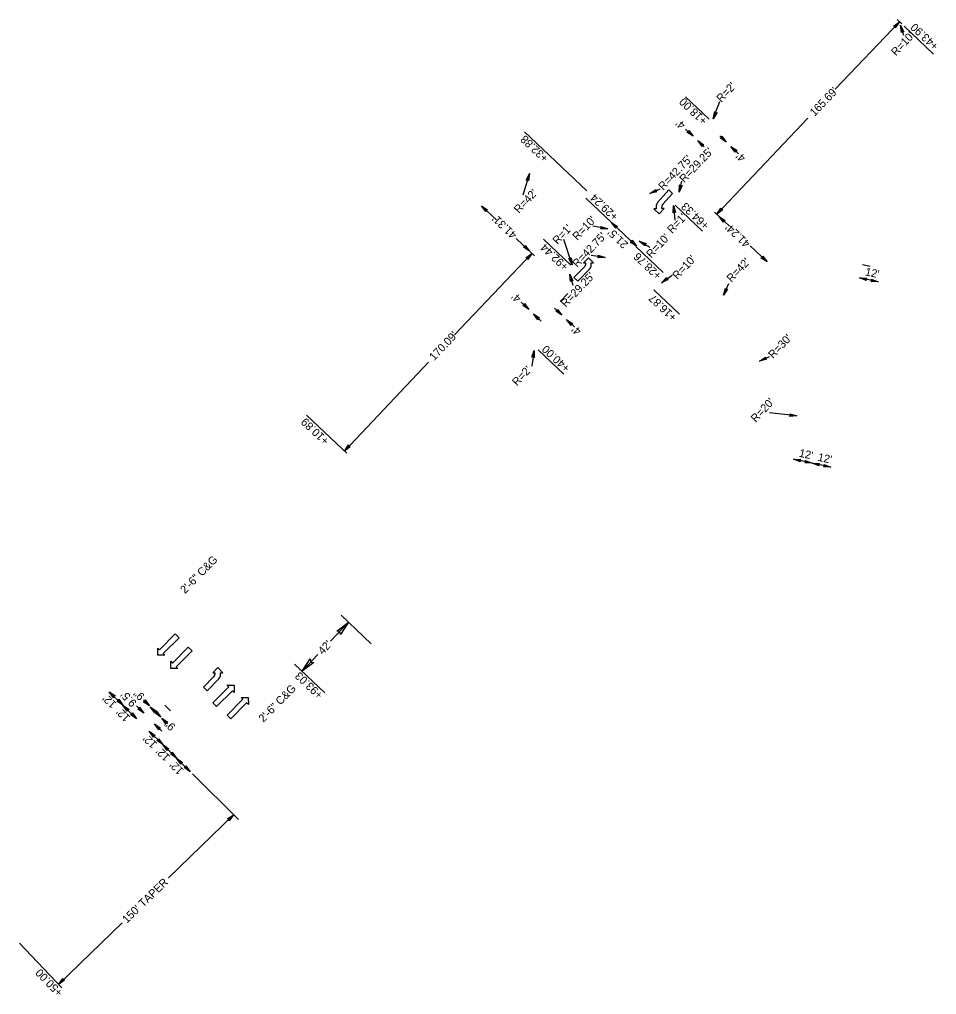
# Model space of a CAD drawing. Extents: x 2320991 to 2332664, y 598057 to 612602.
# Drawn here: x 2327151 to 2327723, y 602418 to 603027 of the extents above; entities that cross this region are included whole.
import ezdxf

# ---------------------------------------------------------------- set-up
doc = ezdxf.new("R2010")
doc.units = 0
for name, color, linetype in [('Prop Dimension', 7, 'Continuous'), ('Prop Dimension Text', 7, 'Continuous'), ('Prop Horizontal Alignment Tick Small', 7, 'Continuous'), ('Prop Lane Arrow CELL', 7, 'Continuous'), ('Prop Terminator CELL', 7, 'Continuous')]:
    doc.layers.add(name, color=color, linetype=linetype)

msp = doc.modelspace()

# ---------------------------------------------------------------- linework, layer by layer
at = {"layer": 'Prop Dimension'}
for p, q in [((2327700.07, 603025.5), (2327660.07, 602983.31)), ((2327701.52, 603024.12), (2327698.62, 603026.87)), ((2327700.84, 603023.33), (2327702.66, 603017)), ((2327702.97, 603022.75), (2327721.44, 603005.24)), ((2327581.34, 602964.58), (2327566.55, 602978.6)), ((2327583.88, 602964.88), (2327587.91, 602975.56)), ((2327642.9, 602965.2), (2327586.07, 602905.26)), ((2327566.56, 602958.44), (2327571.27, 602953.97)), ((2327504.81, 602919.84), (2327465.89, 602956.74)), ((2327587.97, 602954.15), (2327591.96, 602950.35)), ((2327574.17, 602951.21), (2327578.19, 602947.39)), ((2327594.86, 602947.59), (2327599.67, 602943.02)), ((2327469.09, 602930.65), (2327464.93, 602917.11)), ((2327562.55, 602919.06), (2327564.17, 602925.94)), ((2327544.24, 602918.18), (2327550.59, 602921.06)), ((2327439.12, 602910.59), (2327448.5, 602901.69)), ((2327520.27, 602900.17), (2327504.3, 602915.31)), ((2327559.09, 602910.7), (2327559.91, 602901.64)), ((2327560.01, 602910.84), (2327577.1, 602894.64)), ((2327587.52, 602903.88), (2327584.62, 602906.64)), ((2327594, 602897.75), (2327587.52, 602903.88)), ((2327517.95, 602896.18), (2327508.59, 602897.72)), ((2327520.27, 602900.17), (2327535.87, 602885.38)), ((2327460.81, 602890.02), (2327469.1, 602882.17)), ((2327494.95, 602873.46), (2327477.76, 602889.76)), ((2327495.76, 602873.6), (2327490.47, 602889.4)), ((2327537.68, 602888.49), (2327544.31, 602884.76)), ((2327617.45, 602875.51), (2327606.93, 602885.49)), ((2327422.29, 602829.89), (2327470.55, 602880.79)), ((2327469.31, 602881.96), (2327472.22, 602879.21)), ((2327516.32, 602878.3), (2327507.55, 602879.44)), ((2327535.54, 602885.02), (2327552.62, 602868.82)), ((2327494.23, 602867.81), (2327496.16, 602861)), ((2327551.49, 602862.43), (2327558.2, 602867.24)), ((2327590.29, 602854.7), (2327593.54, 602862.02)), ((2327686.9, 602863.02), (2327675.17, 602865.59)), ((2327488.14, 602850.66), (2327492.94, 602855.72)), ((2327546.77, 602857.99), (2327562.81, 602842.79)), ((2327463.98, 602850.24), (2327468.69, 602845.77)), ((2327471.6, 602843.02), (2327476.41, 602838.45)), ((2327484.67, 602846.65), (2327489.38, 602842.18)), ((2327492.29, 602839.43), (2327497.1, 602834.86)), ((2327472.03, 602820.25), (2327470.47, 602810.42)), ((2327474.47, 602820.61), (2327490.44, 602805.47)), ((2327353.53, 602757.36), (2327406.1, 602812.81)), ((2327612.64, 602813.49), (2327618.99, 602816.37)), ((2327352.07, 602758.74), (2327329.88, 602779.77)), ((2327636.13, 602779.33), (2327619.05, 602781.24)), ((2327352.07, 602758.74), (2327354.98, 602755.98)), ((2327645.61, 602749.78), (2327633.88, 602752.35)), ((2327657.33, 602747.22), (2327645.61, 602749.78)), ((2327351.41, 602654.84), (2327370.23, 602636.99)), ((2327344.92, 602638.68), (2327356.06, 602650.43)), ((2327327.09, 602619.88), (2327336.88, 602630.2)), ((2327322.44, 602624.31), (2327341.22, 602606.4)), ((2327206.68, 602607.05), (2327215.21, 602598.61)), ((2327227.97, 602601.9), (2327231.7, 602598.23)), ((2327215.21, 602598.61), (2327223.73, 602590.17)), ((2327223.58, 602598.19), (2327228.21, 602593.62)), ((2327232.23, 602597.7), (2327235.96, 602594.02)), ((2327235.12, 602594.85), (2327238.85, 602591.17)), ((2327234.97, 602586.95), (2327239.59, 602582.38)), ((2327239.39, 602590.64), (2327243.12, 602586.97)), ((2327231.55, 602582.43), (2327240.08, 602573.99)), ((2327240.08, 602573.99), (2327248.61, 602565.54)), ((2327248.61, 602565.54), (2327257.13, 602557.1)), ((2327258.56, 602555.69), (2327287.38, 602527.16)), ((2327243.72, 602490.87), (2327284.31, 602530.19)), ((2327174.97, 602424.29), (2327214.63, 602462.7)), ((2327150.6, 602449.92), (2327176.95, 602422.2))]:
    msp.add_line(p, q, dxfattribs=at)
at = {"layer": 'Prop Horizontal Alignment Tick Small'}
for p, q in [((2327677.02, 602873.85), (2327681.9, 602872.75)), ((2327244.86, 602595.2), (2327241.3, 602598.71))]:
    msp.add_line(p, q, dxfattribs=at)
at = {"layer": 'Prop Lane Arrow CELL'}
for p, q in [((2327556.02, 602920.49), (2327549.02, 602912.6)), ((2327552.41, 602911.46), (2327558.49, 602918.3)), ((2327558.49, 602918.3), (2327556.02, 602920.49)), ((2327548.3, 602908.63), (2327546.81, 602908.54)), ((2327546.81, 602908.54), (2327550.07, 602905.58)), ((2327550.07, 602905.58), (2327553.1, 602908.91)), ((2327553.1, 602908.91), (2327551.61, 602908.83)), ((2327505.97, 602878), (2327502.77, 602874.84)), ((2327502.77, 602874.84), (2327504.25, 602874.84)), ((2327509.06, 602874.87), (2327505.97, 602878)), ((2327507.58, 602874.86), (2327509.06, 602874.87)), ((2327503.31, 602872.26), (2327496.88, 602865.76)), ((2327499.22, 602863.43), (2327506.64, 602870.93)), ((2327496.88, 602865.76), (2327499.22, 602863.43)), ((2327238.01, 602633.22), (2327247.89, 602643.14)), ((2327247.89, 602643.14), (2327250.23, 602640.81)), ((2327250.23, 602640.81), (2327240.35, 602630.89)), ((2327236.99, 602629.79), (2327236.95, 602634.28)), ((2327236.95, 602634.28), (2327238.01, 602633.22)), ((2327241.41, 602629.83), (2327236.99, 602629.79)), ((2327240.35, 602630.89), (2327241.41, 602629.83)), ((2327246.13, 602624.98), (2327256.01, 602634.9)), ((2327258.35, 602632.57), (2327248.47, 602622.65)), ((2327256.01, 602634.9), (2327258.35, 602632.57)), ((2327245.11, 602621.55), (2327245.07, 602626.04)), ((2327245.07, 602626.04), (2327246.13, 602624.98)), ((2327249.53, 602621.6), (2327245.11, 602621.55)), ((2327248.47, 602622.65), (2327249.53, 602621.6)), ((2327274.5, 602622.08), (2327271.3, 602618.91)), ((2327271.3, 602618.91), (2327272.79, 602618.92)), ((2327277.59, 602618.95), (2327274.5, 602622.08)), ((2327276.11, 602618.94), (2327277.59, 602618.95)), ((2327271.85, 602616.34), (2327265.41, 602609.83)), ((2327267.75, 602607.51), (2327275.18, 602615.01)), ((2327280.18, 602611.09), (2327284.6, 602611.13)), ((2327284.6, 602611.13), (2327284.65, 602606.64)), ((2327265.41, 602609.83), (2327267.75, 602607.51)), ((2327271.37, 602600.11), (2327281.25, 602610.03)), ((2327283.58, 602607.7), (2327273.71, 602597.78)), ((2327281.25, 602610.03), (2327280.18, 602611.09)), ((2327284.65, 602606.64), (2327283.58, 602607.7)), ((2327273.71, 602597.78), (2327271.37, 602600.11)), ((2327280.23, 602592.48), (2327290.1, 602602.4)), ((2327292.44, 602600.07), (2327282.57, 602590.15)), ((2327289.04, 602603.46), (2327293.46, 602603.5)), ((2327290.1, 602602.4), (2327289.04, 602603.46)), ((2327293.51, 602599.01), (2327292.44, 602600.07)), ((2327293.46, 602603.5), (2327293.51, 602599.01)), ((2327282.57, 602590.15), (2327280.23, 602592.48))]:
    msp.add_line(p, q, dxfattribs=at)
for centre, radius, start, end in [((2327553.41, 602909.76), 5.25, 147.06281, 192.3745), ((2327554.84, 602909.29), 3.27, 138.38674, 188.04491), ((2327501, 602874.56), 3.27, 315.29506, 4.95323), ((2327502.41, 602874.01), 5.25, 323.97113, 9.28282), ((2327269.54, 602618.64), 3.27, 315.29506, 4.95323), ((2327270.94, 602618.09), 5.25, 323.97113, 9.28282)]:
    msp.add_arc(centre, radius, start, end, dxfattribs=at)
at = {"layer": 'Prop Terminator CELL'}
for points in [[(2327696.41, 603022.77), (2327700.07, 603025.5), (2327697.54, 603021.66), (2327697.35, 603022.63)], [(2327701.34, 603018.79), (2327700.84, 603023.33), (2327702.86, 603019.2), (2327701.93, 603019.53)], [(2327586.19, 602968.81), (2327583.88, 602964.88), (2327584.73, 602969.39), (2327585.27, 602968.57)], [(2327568.55, 602957.63), (2327571.27, 602953.97), (2327567.44, 602956.5), (2327568.41, 602956.69)], [(2327589.23, 602954.01), (2327591.96, 602950.35), (2327588.13, 602952.89), (2327589.1, 602953.07)], [(2327576.9, 602947.55), (2327574.17, 602951.21), (2327578, 602948.67), (2327577.04, 602948.49)], [(2327597.59, 602943.93), (2327594.86, 602947.59), (2327598.69, 602945.06), (2327597.72, 602944.87)], [(2327467.03, 602926.58), (2327469.09, 602930.65), (2327468.53, 602926.09), (2327467.93, 602926.88)], [(2327564.33, 602923.26), (2327562.55, 602919.06), (2327562.81, 602923.65), (2327563.45, 602922.9)], [(2327548.66, 602919.33), (2327544.24, 602918.18), (2327548.03, 602920.78), (2327547.83, 602919.81)], [(2327441.85, 602906.93), (2327439.12, 602910.59), (2327442.95, 602908.06), (2327441.98, 602907.87)], [(2327558.72, 602906.15), (2327559.09, 602910.7), (2327560.29, 602906.27), (2327559.44, 602906.77)], [(2327589.73, 602907.99), (2327586.07, 602905.26), (2327588.61, 602909.09), (2327588.79, 602908.13)], [(2327590.26, 602900.23), (2327587.52, 602903.88), (2327591.36, 602901.35), (2327590.39, 602901.17)], [(2327513.64, 602897.68), (2327517.95, 602896.18), (2327513.36, 602896.13), (2327514.06, 602896.82)], [(2327523, 602896.51), (2327520.27, 602900.17), (2327524.1, 602897.63), (2327523.14, 602897.45)], [(2327466.36, 602885.83), (2327469.1, 602882.17), (2327465.26, 602884.7), (2327466.23, 602884.88)], [(2327533.14, 602889.03), (2327535.87, 602885.38), (2327532.04, 602887.91), (2327533, 602888.09)], [(2327541.22, 602885.61), (2327537.68, 602888.49), (2327542.02, 602886.97), (2327541.12, 602886.55)], [(2327466.89, 602878.06), (2327470.55, 602880.79), (2327468.02, 602876.96), (2327467.83, 602877.92)], [(2327511.96, 602879.65), (2327516.32, 602878.3), (2327511.73, 602878.09), (2327512.4, 602878.81)], [(2327614.72, 602879.17), (2327617.45, 602875.51), (2327613.62, 602878.04), (2327614.59, 602878.23)], [(2327495.07, 602878.11), (2327495.76, 602873.6), (2327493.57, 602877.64), (2327494.51, 602877.35)], [(2327494.71, 602863.27), (2327494.23, 602867.81), (2327496.23, 602863.68), (2327495.31, 602864.01)], [(2327555.6, 602864.42), (2327551.49, 602862.43), (2327554.7, 602865.71), (2327554.7, 602864.73)], [(2327679.4, 602863.87), (2327675.17, 602865.59), (2327679.77, 602865.4), (2327679.03, 602864.74)], [(2327682.67, 602864.74), (2327686.9, 602863.02), (2327682.31, 602863.21), (2327683.04, 602863.87)], [(2327592.82, 602858.5), (2327590.29, 602854.7), (2327591.39, 602859.16), (2327591.89, 602858.31)], [(2327465.96, 602849.43), (2327468.69, 602845.77), (2327464.86, 602848.3), (2327465.83, 602848.49)], [(2327474.33, 602839.36), (2327471.6, 602843.02), (2327475.43, 602840.48), (2327474.46, 602840.3)], [(2327486.65, 602845.84), (2327489.38, 602842.18), (2327485.55, 602844.71), (2327486.52, 602844.9)], [(2327495.02, 602835.77), (2327492.29, 602839.43), (2327496.12, 602836.9), (2327495.15, 602836.71)], [(2327470.56, 602815.93), (2327472.03, 602820.25), (2327472.11, 602815.66), (2327471.41, 602816.35)], [(2327617.05, 602814.64), (2327612.64, 602813.49), (2327616.43, 602816.09), (2327616.23, 602815.12)], [(2327631.74, 602780.6), (2327636.13, 602779.33), (2327631.54, 602779.04), (2327632.2, 602779.77)], [(2327357.18, 602760.09), (2327353.53, 602757.36), (2327356.06, 602761.19), (2327356.24, 602760.23)], [(2327638.11, 602750.63), (2327633.88, 602752.35), (2327638.48, 602752.16), (2327637.74, 602751.51)], [(2327641.38, 602751.5), (2327645.61, 602749.78), (2327641.02, 602749.97), (2327641.75, 602750.63)], [(2327649.84, 602748.06), (2327645.61, 602749.78), (2327650.2, 602749.6), (2327649.47, 602748.94)], [(2327653.1, 602748.94), (2327657.33, 602747.22), (2327652.74, 602747.4), (2327653.47, 602748.06)], [(2327348.74, 602644.97), (2327356.06, 602650.43), (2327350.99, 602642.76), (2327350.62, 602644.7)], [(2327334.4, 602625.34), (2327327.09, 602619.88), (2327332.15, 602627.54), (2327332.52, 602625.61)], [(2327209.33, 602603.34), (2327206.68, 602607.05), (2327210.46, 602604.44), (2327209.49, 602604.27)], [(2327212.55, 602602.33), (2327215.21, 602598.61), (2327211.43, 602601.23), (2327212.4, 602601.39)], [(2327229.04, 602601.94), (2327231.7, 602598.23), (2327227.91, 602600.83), (2327228.88, 602601)], [(2327217.86, 602594.89), (2327215.21, 602598.61), (2327218.99, 602596), (2327218.01, 602595.83)], [(2327221.08, 602593.88), (2327223.73, 602590.17), (2327219.96, 602592.78), (2327220.93, 602592.95)], [(2327225.55, 602597.34), (2327228.21, 602593.62), (2327224.43, 602596.23), (2327225.4, 602596.4)], [(2327234.89, 602593.99), (2327232.23, 602597.7), (2327236.01, 602595.09), (2327235.04, 602594.93)], [(2327236.19, 602594.88), (2327238.85, 602591.17), (2327235.07, 602593.78), (2327236.04, 602593.94)], [(2327237.62, 602583.23), (2327234.97, 602586.95), (2327238.75, 602584.34), (2327237.78, 602584.17)], [(2327242.05, 602586.93), (2327239.39, 602590.64), (2327243.17, 602588.03), (2327242.2, 602587.87)], [(2327234.2, 602578.71), (2327231.55, 602582.43), (2327235.33, 602579.81), (2327234.36, 602579.65)], [(2327237.43, 602577.7), (2327240.08, 602573.99), (2327236.3, 602576.6), (2327237.27, 602576.76)], [(2327242.73, 602570.27), (2327240.08, 602573.99), (2327243.86, 602571.37), (2327242.89, 602571.21)], [(2327245.95, 602569.26), (2327248.61, 602565.54), (2327244.83, 602568.16), (2327245.8, 602568.32)], [(2327251.26, 602561.83), (2327248.61, 602565.54), (2327252.39, 602562.93), (2327251.41, 602562.76)], [(2327254.48, 602560.82), (2327257.13, 602557.1), (2327253.36, 602559.72), (2327254.33, 602559.88)], [(2327280.54, 602527.62), (2327284.31, 602530.19), (2327281.62, 602526.47), (2327281.48, 602527.44)], [(2327178.74, 602426.86), (2327174.97, 602424.29), (2327177.66, 602428.01), (2327177.8, 602427.04)]]:
    msp.add_lwpolyline(points, close=True, dxfattribs=at)

# ---------------------------------------------------------------- texts
at = {"layer": 'Prop Dimension'}
for s, rotation, p in [('+43.90', 136.52652, (2327724.94, 603010.77)), ('+18.00', 136.52652, (2327580.47, 602964.24)), ('+32.88', 136.52652, (2327481.36, 602940.81)), ('+29.24', 136.52652, (2327524.97, 602904.27)), ('+64.33', 136.52652, (2327581.69, 602898.83)), ('+92.44', 136.52652, (2327493.88, 602873.18)), ('+28.76', 136.52652, (2327551.97, 602867.54)), ('+16.87', 136.52652, (2327561.48, 602841.47)), ('+40.00', 136.52652, (2327494.73, 602809.69)), ('+10.89', 136.52652, (2327344.3, 602764.3)), ('+50.00', 134.082, (2327178.02, 602419.65))]:
    msp.add_text(s, height=5, rotation=rotation, dxfattribs=at).set_placement(p)
at = {"layer": 'Prop Dimension Text'}
for s, rotation, p in [("R=10'", 46.52652, (2327697.97, 603003.76)), ("R=2'", 46.52652, (2327588.92, 602974.74)), ("165.69'", 46.29649, (2327647.14, 602966.1)), ("4'", 136.44625, (2327566.86, 602961.45)), ("R=29.25'", 46.52652, (2327565.76, 602924.57)), ("R=42.75'", 46.52652, (2327552.61, 602919.86)), ("4'", 136.44625, (2327604.51, 602940.91)), ("R=42'", 46.52652, (2327462.45, 602905.45)), ("41.31'", 136.29649, (2327461.62, 602892.9)), ("R=10'", 46.52652, (2327498.97, 602888.57)), ("R=1'", 46.52652, (2327558.15, 602892.89)), ("R=1'", 46.52652, (2327486.57, 602886.03)), ("41.24'", 136.29649, (2327607.34, 602887.43)), ("R=42.75'", 46.52652, (2327498.95, 602871.65)), ("21.5'", 135.87888, (2327531.11, 602886.85)), ("R=10'", 46.52652, (2327545.05, 602877.55)), ("R=10'", 46.52652, (2327561.41, 602864.15)), ("R=42'", 46.52652, (2327595.26, 602862.4)), ("R=29.25'", 46.60679, (2327491.76, 602846.77)), ("12'", 347.64979, (2327678.36, 602867.16)), ("4'", 136.52652, (2327464.27, 602853.24)), ("170.09'", 46.29649, (2327409.56, 602813.47)), ("4'", 136.52652, (2327501.95, 602832.76)), ("R=30'", 46.52652, (2327621.25, 602814.75)), ("R=2'", 46.52652, (2327461.3, 602797.69)), ("R=20'", 46.52652, (2327610.35, 602774.92)), ("12'", 347.64979, (2327637.07, 602753.92)), ("12'", 347.64979, (2327648.79, 602751.36)), ('2\'-6" C&G', 45.42432, (2327253.93, 602667.95)), ("42'", 46.29649, (2327340.02, 602629.91)), ('+93.03', 136.29649, (2327340.5, 602605.63)), ('2\'-6" C&G', 45.42432, (2327302.87, 602587.54)), ("9.5'", 133.59097, (2327224.16, 602600.38)), ('9"', 135.40258, (2327229.2, 602604.62)), ("12'", 135.28628, (2327211.62, 602599.65)), ("12'", 135.28628, (2327220.15, 602591.21)), ('9"', 135.40258, (2327248.43, 602585.65)), ("12'", 135.28628, (2327236.91, 602574.62)), ("12'", 135.28628, (2327245.02, 602566.59)), ("12'", 135.28628, (2327253.55, 602558.14)), ("150' TAPER", 44.082, (2327217.6, 602462.1))]:
    msp.add_text(s, height=5, rotation=rotation, dxfattribs=at).set_placement(p)

doc.saveas('drawing.dxf')
